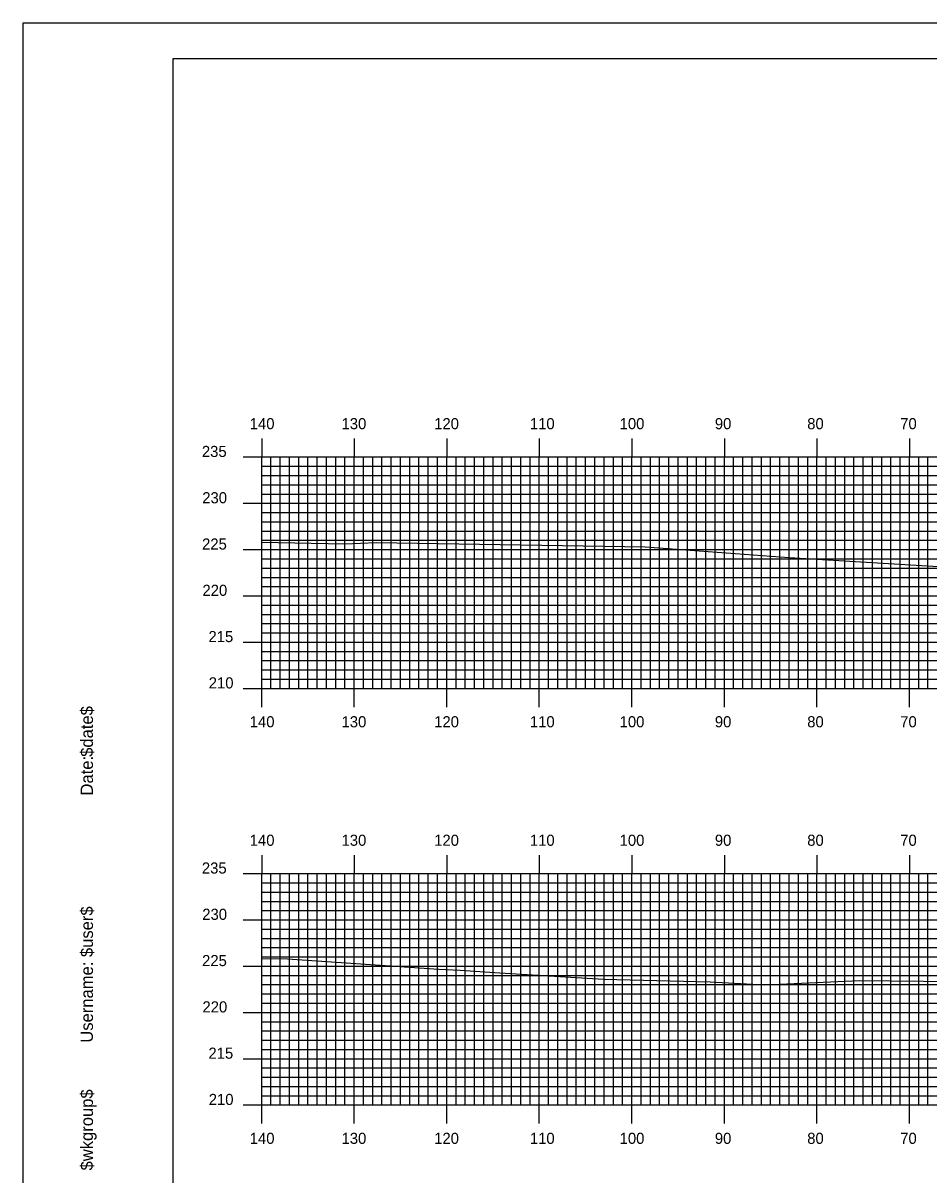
# Model space of a CAD drawing. Extents: x 1820031 to 1820374, y 442591 to 442811.
# Drawn here: x 1820030.9 to 1820128.8, y 442686.1 to 442810.5 of the extents above; entities that cross this region are included whole.
import ezdxf

# ---------------------------------------------------------------- set-up
doc = ezdxf.new("R2010")
doc.units = 0
for name, color, linetype in [('BORDER', 7, 'Continuous'), ('H_V ANNOTATION', 7, 'Continuous'), ('MAJOR', 7, 'Continuous'), ('MINOR', 7, 'Continuous'), ('PLOT BOUNDARY', 7, 'Continuous'), ('S_Roadway_Centerline', 7, 'Continuous')]:
    doc.layers.add(name, color=color, linetype=linetype)

msp = doc.modelspace()

# ---------------------------------------------------------------- linework, layer by layer
at = {"layer": 'BORDER'}
msp.add_lwpolyline([(1820047.09, 442596.67), (1820367.09, 442596.67), (1820367.09, 442806.67), (1820047.09, 442806.67)], close=True, dxfattribs=at)
at = {"layer": 'MAJOR'}
for p, q in [((1820056.69, 442765.67), (1820056.69, 442763.67)), ((1820066.69, 442765.67), (1820066.69, 442763.67)), ((1820076.69, 442765.67), (1820076.69, 442763.67)), ((1820086.69, 442765.67), (1820086.69, 442763.67)), ((1820096.69, 442765.67), (1820096.69, 442763.67)), ((1820106.69, 442765.67), (1820106.69, 442763.67)), ((1820116.69, 442765.67), (1820116.69, 442763.67)), ((1820126.69, 442765.67), (1820126.69, 442763.67)), ((1820054.69, 442763.67), (1820056.69, 442763.67)), ((1820056.69, 442763.67), (1820336.69, 442763.67)), ((1820056.69, 442738.67), (1820056.69, 442763.67)), ((1820056.69, 442738.67), (1820056.69, 442763.67)), ((1820056.69, 442763.67), (1820336.69, 442763.67)), ((1820066.69, 442738.67), (1820066.69, 442763.67)), ((1820076.69, 442738.67), (1820076.69, 442763.67)), ((1820086.69, 442738.67), (1820086.69, 442763.67)), ((1820096.69, 442738.67), (1820096.69, 442763.67)), ((1820106.69, 442738.67), (1820106.69, 442763.67)), ((1820116.69, 442738.67), (1820116.69, 442763.67)), ((1820126.69, 442738.67), (1820126.69, 442763.67)), ((1820054.69, 442758.67), (1820056.69, 442758.67)), ((1820056.69, 442758.67), (1820336.69, 442758.67)), ((1820054.69, 442753.67), (1820056.69, 442753.67)), ((1820056.69, 442753.67), (1820336.69, 442753.67)), ((1820054.69, 442748.67), (1820056.69, 442748.67)), ((1820056.69, 442748.67), (1820336.69, 442748.67)), ((1820054.69, 442743.67), (1820056.69, 442743.67)), ((1820056.69, 442743.67), (1820336.69, 442743.67)), ((1820054.69, 442738.67), (1820056.69, 442738.67)), ((1820056.69, 442738.67), (1820336.69, 442738.67)), ((1820056.69, 442738.67), (1820336.69, 442738.67)), ((1820056.69, 442736.66), (1820056.69, 442738.67)), ((1820066.69, 442736.66), (1820066.69, 442738.67)), ((1820076.69, 442736.66), (1820076.69, 442738.67)), ((1820086.69, 442736.66), (1820086.69, 442738.67)), ((1820096.69, 442736.66), (1820096.69, 442738.67)), ((1820106.69, 442736.66), (1820106.69, 442738.67)), ((1820116.69, 442736.66), (1820116.69, 442738.67)), ((1820126.69, 442736.66), (1820126.69, 442738.67)), ((1820056.69, 442720.67), (1820056.69, 442718.67)), ((1820066.69, 442720.67), (1820066.69, 442718.67)), ((1820076.69, 442720.67), (1820076.69, 442718.67)), ((1820086.69, 442720.67), (1820086.69, 442718.67)), ((1820096.69, 442720.67), (1820096.69, 442718.67)), ((1820106.69, 442720.67), (1820106.69, 442718.67)), ((1820116.69, 442720.67), (1820116.69, 442718.67)), ((1820126.69, 442720.67), (1820126.69, 442718.67)), ((1820054.69, 442718.67), (1820056.69, 442718.67)), ((1820056.69, 442718.67), (1820336.69, 442718.67)), ((1820056.69, 442693.67), (1820056.69, 442718.67)), ((1820056.69, 442693.67), (1820056.69, 442718.67)), ((1820056.69, 442718.67), (1820336.69, 442718.67)), ((1820066.69, 442693.67), (1820066.69, 442718.67)), ((1820076.69, 442693.67), (1820076.69, 442718.67)), ((1820086.69, 442693.67), (1820086.69, 442718.67)), ((1820096.69, 442693.67), (1820096.69, 442718.67)), ((1820106.69, 442693.67), (1820106.69, 442718.67)), ((1820116.69, 442693.67), (1820116.69, 442718.67)), ((1820126.69, 442693.67), (1820126.69, 442718.67)), ((1820054.69, 442713.67), (1820056.69, 442713.67)), ((1820056.69, 442713.67), (1820336.69, 442713.67)), ((1820054.69, 442708.67), (1820056.69, 442708.67)), ((1820056.69, 442708.67), (1820336.69, 442708.67)), ((1820054.69, 442703.67), (1820056.69, 442703.67)), ((1820056.69, 442703.67), (1820336.69, 442703.67)), ((1820054.69, 442698.67), (1820056.69, 442698.67)), ((1820056.69, 442698.67), (1820336.69, 442698.67)), ((1820054.69, 442693.67), (1820056.69, 442693.67)), ((1820056.69, 442693.67), (1820336.69, 442693.67)), ((1820056.69, 442693.67), (1820336.69, 442693.67)), ((1820056.69, 442691.66), (1820056.69, 442693.67)), ((1820066.69, 442691.66), (1820066.69, 442693.67)), ((1820076.69, 442691.66), (1820076.69, 442693.67)), ((1820086.69, 442691.66), (1820086.69, 442693.67)), ((1820096.69, 442691.66), (1820096.69, 442693.67)), ((1820106.69, 442691.66), (1820106.69, 442693.67)), ((1820116.69, 442691.66), (1820116.69, 442693.67)), ((1820126.69, 442691.66), (1820126.69, 442693.67))]:
    msp.add_line(p, q, dxfattribs=at)
at = {"layer": 'MINOR'}
for p, q in [((1820056.69, 442762.67), (1820336.69, 442762.67)), ((1820056.69, 442762.67), (1820058.69, 442762.67)), ((1820057.69, 442738.67), (1820057.69, 442763.67)), ((1820058.69, 442738.67), (1820058.69, 442763.67)), ((1820059.69, 442738.67), (1820059.69, 442763.67)), ((1820060.69, 442738.67), (1820060.69, 442763.67)), ((1820061.69, 442738.67), (1820061.69, 442763.67)), ((1820062.69, 442738.67), (1820062.69, 442763.67)), ((1820063.69, 442738.67), (1820063.69, 442763.67)), ((1820064.69, 442738.67), (1820064.69, 442763.67)), ((1820065.69, 442738.67), (1820065.69, 442763.67)), ((1820067.69, 442738.67), (1820067.69, 442763.67)), ((1820068.69, 442738.67), (1820068.69, 442763.67)), ((1820069.69, 442738.67), (1820069.69, 442763.67)), ((1820070.69, 442738.67), (1820070.69, 442763.67)), ((1820071.69, 442738.67), (1820071.69, 442763.67)), ((1820072.69, 442738.67), (1820072.69, 442763.67)), ((1820073.69, 442738.67), (1820073.69, 442763.67)), ((1820074.69, 442738.67), (1820074.69, 442763.67)), ((1820075.69, 442738.67), (1820075.69, 442763.67)), ((1820077.69, 442738.67), (1820077.69, 442763.67)), ((1820078.69, 442738.67), (1820078.69, 442763.67)), ((1820079.69, 442738.67), (1820079.69, 442763.67)), ((1820080.69, 442738.67), (1820080.69, 442763.67)), ((1820081.69, 442738.67), (1820081.69, 442763.67)), ((1820082.69, 442738.67), (1820082.69, 442763.67)), ((1820083.69, 442738.67), (1820083.69, 442763.67)), ((1820084.69, 442738.67), (1820084.69, 442763.67)), ((1820085.69, 442738.67), (1820085.69, 442763.67)), ((1820087.69, 442738.67), (1820087.69, 442763.67)), ((1820088.69, 442738.67), (1820088.69, 442763.67)), ((1820089.69, 442738.67), (1820089.69, 442763.67)), ((1820090.69, 442738.67), (1820090.69, 442763.67)), ((1820091.69, 442738.67), (1820091.69, 442763.67)), ((1820092.69, 442738.67), (1820092.69, 442763.67)), ((1820093.69, 442738.67), (1820093.69, 442763.67)), ((1820094.69, 442738.67), (1820094.69, 442763.67)), ((1820095.69, 442738.67), (1820095.69, 442763.67)), ((1820097.69, 442738.67), (1820097.69, 442763.67)), ((1820098.69, 442738.67), (1820098.69, 442763.67)), ((1820099.69, 442738.67), (1820099.69, 442763.67)), ((1820100.69, 442738.67), (1820100.69, 442763.67)), ((1820101.69, 442738.67), (1820101.69, 442763.67)), ((1820102.69, 442738.67), (1820102.69, 442763.67)), ((1820103.69, 442738.67), (1820103.69, 442763.67)), ((1820104.69, 442738.67), (1820104.69, 442763.67)), ((1820105.69, 442738.67), (1820105.69, 442763.67)), ((1820107.69, 442738.67), (1820107.69, 442763.67)), ((1820108.69, 442738.67), (1820108.69, 442763.67)), ((1820109.69, 442738.67), (1820109.69, 442763.67)), ((1820110.69, 442738.67), (1820110.69, 442763.67)), ((1820111.69, 442738.67), (1820111.69, 442763.67)), ((1820112.69, 442738.67), (1820112.69, 442763.67)), ((1820113.69, 442738.67), (1820113.69, 442763.67)), ((1820114.69, 442738.67), (1820114.69, 442763.67)), ((1820115.69, 442738.67), (1820115.69, 442763.67)), ((1820117.69, 442738.67), (1820117.69, 442763.67)), ((1820118.69, 442738.67), (1820118.69, 442763.67)), ((1820119.69, 442738.67), (1820119.69, 442763.67)), ((1820120.69, 442738.67), (1820120.69, 442763.67)), ((1820121.69, 442738.67), (1820121.69, 442763.67)), ((1820122.69, 442738.67), (1820122.69, 442763.67)), ((1820123.69, 442738.67), (1820123.69, 442763.67)), ((1820124.69, 442738.67), (1820124.69, 442763.67)), ((1820125.69, 442738.67), (1820125.69, 442763.67)), ((1820127.69, 442738.67), (1820127.69, 442763.67)), ((1820128.69, 442738.67), (1820128.69, 442763.67)), ((1820056.69, 442761.67), (1820336.69, 442761.67)), ((1820056.69, 442761.67), (1820058.69, 442761.67)), ((1820056.69, 442760.67), (1820336.69, 442760.67)), ((1820056.69, 442760.67), (1820058.69, 442760.67)), ((1820056.69, 442759.67), (1820336.69, 442759.67)), ((1820056.69, 442759.67), (1820058.69, 442759.67)), ((1820056.69, 442757.67), (1820336.69, 442757.67)), ((1820056.69, 442757.67), (1820058.69, 442757.67)), ((1820056.69, 442756.67), (1820336.69, 442756.67)), ((1820056.69, 442756.67), (1820058.69, 442756.67)), ((1820056.69, 442755.67), (1820336.69, 442755.67)), ((1820056.69, 442755.67), (1820058.69, 442755.67)), ((1820056.69, 442754.67), (1820336.69, 442754.67)), ((1820056.69, 442754.67), (1820058.69, 442754.67)), ((1820056.69, 442752.67), (1820336.69, 442752.67)), ((1820056.69, 442752.67), (1820058.69, 442752.67)), ((1820056.69, 442751.67), (1820336.69, 442751.67)), ((1820056.69, 442751.67), (1820058.69, 442751.67)), ((1820056.69, 442750.67), (1820336.69, 442750.67)), ((1820056.69, 442750.67), (1820058.69, 442750.67)), ((1820056.69, 442749.67), (1820336.69, 442749.67)), ((1820056.69, 442749.67), (1820058.69, 442749.67)), ((1820056.69, 442747.67), (1820336.69, 442747.67)), ((1820056.69, 442747.67), (1820058.69, 442747.67)), ((1820056.69, 442746.67), (1820336.69, 442746.67)), ((1820056.69, 442746.67), (1820058.69, 442746.67)), ((1820056.69, 442745.67), (1820336.69, 442745.67)), ((1820056.69, 442745.67), (1820058.69, 442745.67)), ((1820056.69, 442744.67), (1820336.69, 442744.67)), ((1820056.69, 442744.67), (1820058.69, 442744.67)), ((1820056.69, 442742.67), (1820336.69, 442742.67)), ((1820056.69, 442742.67), (1820058.69, 442742.67)), ((1820056.69, 442741.67), (1820336.69, 442741.67)), ((1820056.69, 442741.67), (1820058.69, 442741.67)), ((1820056.69, 442740.67), (1820336.69, 442740.67)), ((1820056.69, 442740.67), (1820058.69, 442740.67)), ((1820056.69, 442739.67), (1820336.69, 442739.67)), ((1820056.69, 442739.67), (1820058.69, 442739.67)), ((1820057.69, 442693.67), (1820057.69, 442718.67)), ((1820058.69, 442693.67), (1820058.69, 442718.67)), ((1820059.69, 442693.67), (1820059.69, 442718.67)), ((1820060.69, 442693.67), (1820060.69, 442718.67)), ((1820061.69, 442693.67), (1820061.69, 442718.67)), ((1820062.69, 442693.67), (1820062.69, 442718.67)), ((1820063.69, 442693.67), (1820063.69, 442718.67)), ((1820064.69, 442693.67), (1820064.69, 442718.67)), ((1820065.69, 442693.67), (1820065.69, 442718.67)), ((1820067.69, 442693.67), (1820067.69, 442718.67)), ((1820068.69, 442693.67), (1820068.69, 442718.67)), ((1820069.69, 442693.67), (1820069.69, 442718.67)), ((1820070.69, 442693.67), (1820070.69, 442718.67)), ((1820071.69, 442693.67), (1820071.69, 442718.67)), ((1820072.69, 442693.67), (1820072.69, 442718.67)), ((1820073.69, 442693.67), (1820073.69, 442718.67)), ((1820074.69, 442693.67), (1820074.69, 442718.67)), ((1820075.69, 442693.67), (1820075.69, 442718.67)), ((1820077.69, 442693.67), (1820077.69, 442718.67)), ((1820078.69, 442693.67), (1820078.69, 442718.67)), ((1820079.69, 442693.67), (1820079.69, 442718.67)), ((1820080.69, 442693.67), (1820080.69, 442718.67)), ((1820081.69, 442693.67), (1820081.69, 442718.67)), ((1820082.69, 442693.67), (1820082.69, 442718.67)), ((1820083.69, 442693.67), (1820083.69, 442718.67)), ((1820084.69, 442693.67), (1820084.69, 442718.67)), ((1820085.69, 442693.67), (1820085.69, 442718.67)), ((1820087.69, 442693.67), (1820087.69, 442718.67)), ((1820088.69, 442693.67), (1820088.69, 442718.67)), ((1820089.69, 442693.67), (1820089.69, 442718.67)), ((1820090.69, 442693.67), (1820090.69, 442718.67)), ((1820091.69, 442693.67), (1820091.69, 442718.67)), ((1820092.69, 442693.67), (1820092.69, 442718.67)), ((1820093.69, 442693.67), (1820093.69, 442718.67)), ((1820094.69, 442693.67), (1820094.69, 442718.67)), ((1820095.69, 442693.67), (1820095.69, 442718.67)), ((1820097.69, 442693.67), (1820097.69, 442718.67)), ((1820098.69, 442693.67), (1820098.69, 442718.67)), ((1820099.69, 442693.67), (1820099.69, 442718.67)), ((1820100.69, 442693.67), (1820100.69, 442718.67)), ((1820101.69, 442693.67), (1820101.69, 442718.67)), ((1820102.69, 442693.67), (1820102.69, 442718.67)), ((1820103.69, 442693.67), (1820103.69, 442718.67)), ((1820104.69, 442693.67), (1820104.69, 442718.67)), ((1820105.69, 442693.67), (1820105.69, 442718.67)), ((1820107.69, 442693.67), (1820107.69, 442718.67)), ((1820108.69, 442693.67), (1820108.69, 442718.67)), ((1820109.69, 442693.67), (1820109.69, 442718.67)), ((1820110.69, 442693.67), (1820110.69, 442718.67)), ((1820111.69, 442693.67), (1820111.69, 442718.67)), ((1820112.69, 442693.67), (1820112.69, 442718.67)), ((1820113.69, 442693.67), (1820113.69, 442718.67)), ((1820114.69, 442693.67), (1820114.69, 442718.67)), ((1820115.69, 442693.67), (1820115.69, 442718.67)), ((1820117.69, 442693.67), (1820117.69, 442718.67)), ((1820118.69, 442693.67), (1820118.69, 442718.67)), ((1820119.69, 442693.67), (1820119.69, 442718.67)), ((1820120.69, 442693.67), (1820120.69, 442718.67)), ((1820121.69, 442693.67), (1820121.69, 442718.67)), ((1820122.69, 442693.67), (1820122.69, 442718.67)), ((1820123.69, 442693.67), (1820123.69, 442718.67)), ((1820124.69, 442693.67), (1820124.69, 442718.67)), ((1820125.69, 442693.67), (1820125.69, 442718.67)), ((1820127.69, 442693.67), (1820127.69, 442718.67)), ((1820128.69, 442693.67), (1820128.69, 442718.67)), ((1820056.69, 442717.67), (1820336.69, 442717.67)), ((1820056.69, 442717.67), (1820058.69, 442717.67)), ((1820056.69, 442716.67), (1820336.69, 442716.67)), ((1820056.69, 442716.67), (1820058.69, 442716.67)), ((1820056.69, 442715.67), (1820336.69, 442715.67)), ((1820056.69, 442715.67), (1820058.69, 442715.67)), ((1820056.69, 442714.67), (1820336.69, 442714.67)), ((1820056.69, 442714.67), (1820058.69, 442714.67)), ((1820056.69, 442712.67), (1820336.69, 442712.67)), ((1820056.69, 442712.67), (1820058.69, 442712.67)), ((1820056.69, 442711.67), (1820336.69, 442711.67)), ((1820056.69, 442711.67), (1820058.69, 442711.67)), ((1820056.69, 442710.67), (1820336.69, 442710.67)), ((1820056.69, 442710.67), (1820058.69, 442710.67)), ((1820056.69, 442709.67), (1820336.69, 442709.67)), ((1820056.69, 442709.67), (1820058.69, 442709.67)), ((1820056.69, 442707.67), (1820336.69, 442707.67)), ((1820056.69, 442707.67), (1820058.69, 442707.67)), ((1820056.69, 442706.67), (1820336.69, 442706.67)), ((1820056.69, 442706.67), (1820058.69, 442706.67)), ((1820056.69, 442705.67), (1820336.69, 442705.67)), ((1820056.69, 442705.67), (1820058.69, 442705.67)), ((1820056.69, 442704.67), (1820336.69, 442704.67)), ((1820056.69, 442704.67), (1820058.69, 442704.67)), ((1820056.69, 442702.67), (1820336.69, 442702.67)), ((1820056.69, 442702.67), (1820058.69, 442702.67)), ((1820056.69, 442701.67), (1820336.69, 442701.67)), ((1820056.69, 442701.67), (1820058.69, 442701.67)), ((1820056.69, 442700.67), (1820336.69, 442700.67)), ((1820056.69, 442700.67), (1820058.69, 442700.67)), ((1820056.69, 442699.67), (1820336.69, 442699.67)), ((1820056.69, 442699.67), (1820058.69, 442699.67)), ((1820056.69, 442697.67), (1820336.69, 442697.67)), ((1820056.69, 442697.67), (1820058.69, 442697.67)), ((1820056.69, 442696.67), (1820336.69, 442696.67)), ((1820056.69, 442696.67), (1820058.69, 442696.67)), ((1820056.69, 442695.67), (1820336.69, 442695.67)), ((1820056.69, 442695.67), (1820058.69, 442695.67)), ((1820056.69, 442694.67), (1820336.69, 442694.67)), ((1820056.69, 442694.67), (1820058.69, 442694.67))]:
    msp.add_line(p, q, dxfattribs=at)
at = {"layer": 'PLOT BOUNDARY'}
msp.add_lwpolyline([(1820030.9, 442590.55), (1820370.9, 442590.55), (1820370.9, 442810.55), (1820030.9, 442810.55)], close=True, dxfattribs=at)
at = {"layer": 'S_Roadway_Centerline'}
for points in [[(1820056.69, 442754.46), (1820062.03, 442754.36), (1820063.89, 442754.33), (1820065.67, 442754.29), (1820069.06, 442754.43), (1820098.12, 442753.95), (1820113.68, 442752.8), (1820132.79, 442751.65), (1820134.29, 442751.55), (1820140.62, 442751.49), (1820149.41, 442751.38), (1820151.92, 442751.32), (1820165.5, 442751.36), (1820174.38, 442750.71), (1820182.55, 442750.44), (1820197.57, 442749.67), (1820199.21, 442749.66), (1820199.99, 442749.57), (1820203.77, 442749.42), (1820233.29, 442748.15), (1820241.27, 442747.91), (1820249.59, 442747.83), (1820279.36, 442747.36)], [(1820056.69, 442709.5), (1820059.48, 442709.47), (1820075.85, 442708.33), (1820078.14, 442708.24), (1820082.42, 442707.93), (1820093.62, 442707.28), (1820105.14, 442706.97), (1820111.07, 442706.66), (1820121.31, 442707.11), (1820141.91, 442706.91)]]:
    msp.add_lwpolyline(points, dxfattribs=at)

# ---------------------------------------------------------------- texts
at = {"layer": 'BORDER'}
for s, p in [('$date$', (1820038.46, 442731.28)), ('Date:', (1820038.46, 442727.1)), ('$user$', (1820038.46, 442709.65)), ('Username:', (1820038.46, 442700.4)), ('$wkgroup$', (1820038.46, 442686.6))]:
    msp.add_text(s, height=1.339, rotation=90, dxfattribs=at).set_placement(p)
at = {"layer": 'H_V ANNOTATION'}
for s, p in [('140', (1820055.4, 442766.67)), ('130', (1820065.32, 442766.67)), ('120', (1820075.33, 442766.67)), ('110', (1820085.67, 442766.67)), ('100', (1820095.37, 442766.67)), ('90', (1820105.66, 442766.67)), ('80', (1820115.64, 442766.67)), ('70', (1820125.69, 442766.67)), ('235', (1820050.23, 442763.67)), ('230', (1820050.27, 442758.67)), ('225', (1820050.25, 442753.67)), ('220', (1820050.29, 442748.67)), ('215', (1820050.94, 442743.67)), ('210', (1820050.97, 442738.67)), ('140', (1820055.4, 442734.47)), ('130', (1820065.32, 442734.47)), ('120', (1820075.33, 442734.47)), ('110', (1820085.67, 442734.47)), ('100', (1820095.37, 442734.47)), ('90', (1820105.66, 442734.47)), ('80', (1820115.64, 442734.47)), ('70', (1820125.69, 442734.47)), ('140', (1820055.4, 442721.67)), ('130', (1820065.32, 442721.67)), ('120', (1820075.33, 442721.67)), ('110', (1820085.67, 442721.67)), ('100', (1820095.37, 442721.67)), ('90', (1820105.66, 442721.67)), ('80', (1820115.64, 442721.67)), ('70', (1820125.69, 442721.67)), ('235', (1820050.23, 442718.67)), ('230', (1820050.27, 442713.67)), ('225', (1820050.25, 442708.67)), ('220', (1820050.29, 442703.67)), ('215', (1820050.94, 442698.67)), ('210', (1820050.97, 442693.67)), ('140', (1820055.4, 442689.47)), ('130', (1820065.32, 442689.47)), ('120', (1820075.33, 442689.47)), ('110', (1820085.67, 442689.47)), ('100', (1820095.37, 442689.47)), ('90', (1820105.66, 442689.47)), ('80', (1820115.64, 442689.47)), ('70', (1820125.69, 442689.47))]:
    msp.add_text(s, height=1.2, dxfattribs=at).set_placement(p)
at = {"layer": 'MAJOR'}
for p in [(1820056.68, 442738.67), (1820056.68, 442693.67)]:
    msp.add_text('-', height=0.012, dxfattribs=at).set_placement(p)

doc.saveas('drawing.dxf')
